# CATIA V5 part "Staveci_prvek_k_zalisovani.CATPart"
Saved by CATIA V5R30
Part number: Staveci_prvek_k_zalisovani
Definition: E 1265_6_1
Nomenclature: E 1265_6_1
Source: Unknown
Description: PART-E 1265_6_1-DESC
Bounding box of the stored display mesh (mm): x -3.25 to 3.25, y -3.241 to 3.241, z -7 to 1.8
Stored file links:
  E:\Bakalarka\Model\Forma_v7\Staveci_prvek_k_zalisovani.CATPart
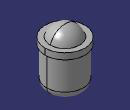
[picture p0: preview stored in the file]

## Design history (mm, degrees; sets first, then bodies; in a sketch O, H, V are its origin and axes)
Body1 "E 1265_6" (main body)
  Solid1: solid without history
